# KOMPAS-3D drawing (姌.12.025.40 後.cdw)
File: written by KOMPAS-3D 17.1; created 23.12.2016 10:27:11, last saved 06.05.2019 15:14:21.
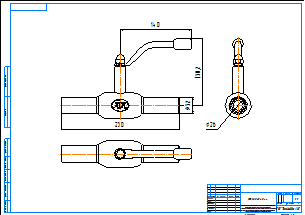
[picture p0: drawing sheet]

Sheet 1: A2, landscape

Title block, sheet 1: name: КШ.12.025.40 сс; material: Внимание! Данный продукт является объектом авторского права ООО «Торговый Дом АДЛ». / Запрещается изменение, копирование, распространение / (в том числе путем копирования на другие сайты и ресурсы в Интернете) / или любое иное использование информации и объектов без предварительного / согласия правообладателя (ООО «Торговый Дом АДЛ»).; sheets: 1; organisation: ООО "Торговый дом АДЛ"; sheet format: A2; stored path: C:\Users\tra\Desktop\2д чертежи\Шаровые краны БИВАЛ\КШ_Бивал_серия_11_12\KOMPAS_2D\КШ.12.025.40 сс.cdw

Views: Спереди 4, Проекционный вид 5, Проекционный вид 6
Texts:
  Klimkovich
  ADL
Dimensions and other numbers on the sheet: 230; 32; 140; 130,2; 26; 1:1; 1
